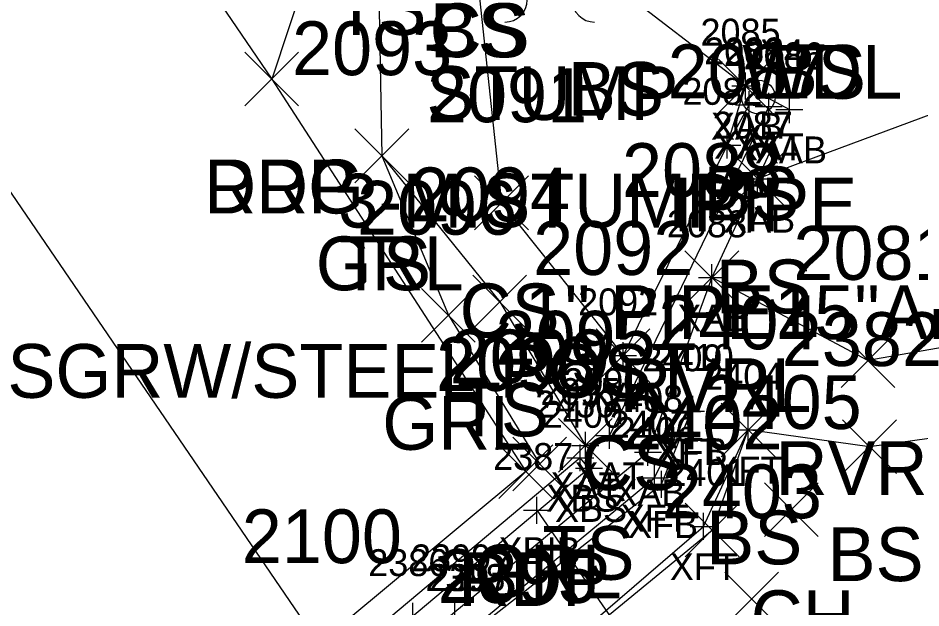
# Model space of a CAD drawing. Extents: x 1501299 to 1502485, y 381423 to 383765.
# Drawn here: x 1501597.62 to 1501631.17, y 383313.75 to 383335.68 of the extents above; entities that cross this region are included whole.
import ezdxf

# ---------------------------------------------------------------- set-up
doc = ezdxf.new("R2010")
doc.units = 0
for name, color, linetype in [('B_A', 7, 'Continuous'), ('B_I', 7, 'Continuous'), ('B_TIC', 7, 'Continuous'), ('BB', 7, 'Continuous'), ('BFT', 7, 'Continuous'), ('BSE', 7, 'Continuous'), ('BSUBM', 7, 'Continuous'), ('L_A', 7, 'Continuous'), ('L_C', 7, 'Continuous'), ('L_I', 7, 'Continuous'), ('L_TIC', 7, 'Continuous'), ('LAWE', 7, 'Continuous'), ('LELB', 7, 'Continuous'), ('LTS', 7, 'Continuous'), ('M_A', 7, 'Continuous'), ('M_C', 7, 'Continuous'), ('MPIP', 7, 'Continuous'), ('P_A', 7, 'Continuous'), ('P_I', 7, 'Continuous'), ('P_TIC', 7, 'Continuous'), ('PET', 7, 'Continuous'), ('PRC', 7, 'Continuous'), ('R_A', 7, 'Continuous'), ('R_C', 7, 'Continuous'), ('R_I', 7, 'Continuous'), ('R_TIC', 7, 'Continuous'), ('RDG', 7, 'Continuous'), ('RGR', 7, 'Continuous')]:
    doc.layers.add(name, color=color, linetype=linetype)

msp = doc.modelspace()

# ---------------------------------------------------------------- linework, layer by layer
at = {"layer": 'B_TIC'}
for p, q in [((1501624.647, 383333.16), (1501624.722, 383333.16)), ((1501624.781, 383332.46), (1501624.857, 383332.46)), ((1501625.516, 383332.398), (1501625.591, 383332.398)), ((1501626.279, 383332.279), (1501626.355, 383332.279)), ((1501623.974, 383330.957), (1501624.05, 383330.957)), ((1501623.974, 383330.957), (1501624.05, 383330.957)), ((1501623.974, 383330.957), (1501624.05, 383330.957)), ((1501625.099, 383329.703), (1501625.175, 383329.703)), ((1501623.399, 383326.029), (1501623.475, 383326.029)), ((1501620.1, 383323.129), (1501620.176, 383323.129)), ((1501622.491, 383321.046), (1501622.566, 383321.046)), ((1501622.626, 383321.06), (1501622.702, 383321.06)), ((1501624.75, 383320.366), (1501624.826, 383320.366)), ((1501619.591, 383320.161), (1501619.667, 383320.161)), ((1501618.699, 383319.793), (1501618.775, 383319.793)), ((1501618.511, 383319.328), (1501618.586, 383319.328)), ((1501621.024, 383319.534), (1501621.1, 383319.534)), ((1501621.024, 383319.534), (1501621.1, 383319.534)), ((1501618.832, 383318.945), (1501618.908, 383318.945)), ((1501621.272, 383318.583), (1501621.347, 383318.583)), ((1501621.523, 383318.346), (1501621.599, 383318.346)), ((1501616.903, 383317.377), (1501616.979, 383317.377)), ((1501623.094, 383316.78), (1501623.169, 383316.78))]:
    msp.add_line(p, q, dxfattribs=at)
for points in [[(1501624.643, 383332.66), (1501624.643, 383333.66)], [(1501624.143, 383333.16), (1501625.143, 383333.16)], [(1501624.778, 383331.96), (1501624.778, 383332.96)], [(1501625.512, 383331.898), (1501625.512, 383332.898)], [(1501626.276, 383331.779), (1501626.276, 383332.779)], [(1501624.278, 383332.46), (1501625.278, 383332.46)], [(1501625.012, 383332.398), (1501626.012, 383332.398)], [(1501625.776, 383332.279), (1501626.776, 383332.279)], [(1501623.971, 383330.457), (1501623.971, 383331.457)], [(1501623.971, 383330.457), (1501623.971, 383331.457)], [(1501623.971, 383330.457), (1501623.971, 383331.457)], [(1501623.471, 383330.957), (1501624.471, 383330.957)], [(1501623.471, 383330.957), (1501624.471, 383330.957)], [(1501623.471, 383330.957), (1501624.471, 383330.957)], [(1501625.096, 383329.203), (1501625.096, 383330.203)], [(1501624.596, 383329.703), (1501625.596, 383329.703)], [(1501623.396, 383325.529), (1501623.396, 383326.529)], [(1501622.896, 383326.029), (1501623.896, 383326.029)], [(1501620.097, 383322.629), (1501620.097, 383323.629)], [(1501619.597, 383323.129), (1501620.597, 383323.129)], [(1501622.487, 383320.546), (1501622.487, 383321.546)], [(1501622.623, 383320.56), (1501622.623, 383321.56)], [(1501621.987, 383321.046), (1501622.987, 383321.046)], [(1501622.123, 383321.06), (1501623.123, 383321.06)], [(1501619.588, 383319.661), (1501619.588, 383320.661)], [(1501624.747, 383319.866), (1501624.747, 383320.866)], [(1501624.247, 383320.366), (1501625.247, 383320.366)], [(1501618.696, 383319.293), (1501618.696, 383320.293)], [(1501619.088, 383320.161), (1501620.088, 383320.161)], [(1501621.021, 383319.034), (1501621.021, 383320.034)], [(1501621.021, 383319.034), (1501621.021, 383320.034)], [(1501618.196, 383319.793), (1501619.196, 383319.793)], [(1501618.507, 383318.828), (1501618.507, 383319.828)], [(1501618.007, 383319.328), (1501619.007, 383319.328)], [(1501618.829, 383318.445), (1501618.829, 383319.445)], [(1501620.521, 383319.534), (1501621.521, 383319.534)], [(1501620.521, 383319.534), (1501621.521, 383319.534)], [(1501621.268, 383318.083), (1501621.268, 383319.083)], [(1501618.329, 383318.945), (1501619.329, 383318.945)], [(1501621.52, 383317.846), (1501621.52, 383318.846)], [(1501620.768, 383318.583), (1501621.768, 383318.583)], [(1501621.02, 383318.346), (1501622.02, 383318.346)], [(1501616.9, 383316.877), (1501616.9, 383317.877)], [(1501616.4, 383317.377), (1501617.4, 383317.377)], [(1501623.09, 383316.28), (1501623.09, 383317.28)], [(1501622.59, 383316.78), (1501623.59, 383316.78)], [(1501612.287, 383312.93), (1501612.287, 383313.93)], [(1501613.853, 383313.107), (1501613.853, 383314.107)]]:
    msp.add_lwpolyline(points, dxfattribs=at)
at = {"layer": 'BB'}
msp.add_lwpolyline([(1501616.9, 383317.377), (1501632.264, 383295.097)], dxfattribs=at)
at = {"layer": 'BFT'}
for points in [[(1501591.846, 383302.634), (1501599.551, 383300.612), (1501608.842, 383308.268), (1501614.526, 383312.873), (1501621.52, 383318.346), (1501622.623, 383321.06)], [(1501591.893, 383302.71), (1501599.583, 383300.737), (1501608.715, 383308.273), (1501614.382, 383312.876), (1501621.268, 383318.583), (1501622.487, 383321.046)], [(1501590.258, 383300.858), (1501600.794, 383298.267), (1501604.985, 383301.7), (1501610.419, 383306.178), (1501616.429, 383311.032), (1501623.09, 383316.78), (1501624.747, 383320.366)]]:
    msp.add_lwpolyline(points, dxfattribs=at)
at = {"layer": 'BSE'}
msp.add_lwpolyline([(1501600.967, 383303.93), (1501618.829, 383318.945), (1501618.507, 383319.328), (1501600.646, 383304.313)], dxfattribs=at)
at = {"layer": 'BSUBM'}
for points in [[(1501623.971, 383330.957), (1501624.643, 383333.16), (1501626.276, 383332.279), (1501625.096, 383329.703), (1501623.396, 383326.029), (1501621.021, 383319.534)], [(1501623.971, 383330.957), (1501624.778, 383332.46), (1501625.512, 383332.398), (1501619.588, 383320.161), (1501618.696, 383319.793)], [(1501623.971, 383330.957), (1501620.097, 383323.129)], [(1501594.927, 383305.277), (1501590.251, 383306.118), (1501586.94, 383306.811), (1501586.804, 383304.65), (1501587.899, 383304.381), (1501591.885, 383303.599), (1501600.149, 383301.969), (1501608.182, 383308.826), (1501613.853, 383313.607), (1501621.021, 383319.534)]]:
    msp.add_lwpolyline(points, dxfattribs=at)
at = {"layer": 'L_TIC'}
for points in [[(1501623.643, 383332.16), (1501625.643, 383334.16)], [(1501625.643, 383332.16), (1501623.643, 383334.16)], [(1501610.136, 383329.56), (1501612.136, 383331.56)], [(1501612.136, 383329.56), (1501610.136, 383331.56)], [(1501624.096, 383328.703), (1501626.096, 383330.703)], [(1501626.096, 383328.703), (1501624.096, 383330.703)], [(1501614.583, 383327.811), (1501616.583, 383329.811)], [(1501616.583, 383327.811), (1501614.583, 383329.811)], [(1501622.396, 383325.029), (1501624.396, 383327.029)], [(1501624.396, 383325.029), (1501622.396, 383327.029)], [(1501614.516, 383324.125), (1501616.516, 383326.125)], [(1501616.516, 383324.125), (1501614.516, 383326.125)], [(1501619.097, 383322.129), (1501621.097, 383324.129)], [(1501621.097, 383322.129), (1501619.097, 383324.129)], [(1501628.198, 383321.948), (1501630.198, 383323.948)], [(1501630.198, 383321.948), (1501628.198, 383323.948)], [(1501623.747, 383319.366), (1501625.747, 383321.366)], [(1501625.747, 383319.366), (1501623.747, 383321.366)], [(1501623.747, 383319.366), (1501625.747, 383321.366)], [(1501625.747, 383319.366), (1501623.747, 383321.366)], [(1501617.696, 383318.793), (1501619.696, 383320.793)], [(1501619.696, 383318.793), (1501617.696, 383320.793)], [(1501628.255, 383318.743), (1501630.255, 383320.743)], [(1501630.255, 383318.743), (1501628.255, 383320.743)], [(1501625.351, 383316.401), (1501627.351, 383318.401)], [(1501627.351, 383316.401), (1501625.351, 383318.401)], [(1501622.409, 383315.642), (1501624.409, 383317.642)], [(1501624.409, 383315.642), (1501622.409, 383317.642)], [(1501623.877, 383313.082), (1501625.877, 383315.082)], [(1501625.877, 383313.082), (1501623.877, 383315.082)]]:
    msp.add_lwpolyline(points, dxfattribs=at)
at = {"layer": 'LAWE'}
msp.add_lwpolyline([(1501751.7, 383384.782), (1501736.295, 383377.69), (1501721.533, 383363.11), (1501708.276, 383357.65), (1501696.432, 383349.133), (1501679.062, 383342.719), (1501664.765, 383337.172), (1501649.638, 383330.877), (1501644.08, 383325.549), (1501629.198, 383322.948), (1501623.396, 383326.029)], dxfattribs=at)
at = {"layer": 'LELB'}
for points in [[(1501755, 383383.033), (1501740.914, 383377.326), (1501726.442, 383366.412), (1501710.788, 383355.524), (1501696.826, 383347.405), (1501681.956, 383338.634), (1501665.785, 383334.622), (1501652.745, 383328.441), (1501646.391, 383322.759), (1501637.585, 383320.905), (1501629.255, 383319.743), (1501624.747, 383320.366)], [(1501644.375, 383366.495), (1501627.025, 383352.911), (1501621.074, 383344.333), (1501614.47, 383339.228), (1501619.607, 383337.048), (1501624.643, 383333.16)], [(1501625.853, 383354.693), (1501616.397, 383345.622), (1501610.965, 383340.056), (1501611.136, 383330.56), (1501615.516, 383325.125), (1501618.696, 383319.793)], [(1501614.47, 383339.228), (1501615.583, 383328.811), (1501620.097, 383323.129)], [(1501637.668, 383334.383), (1501625.096, 383329.703)], [(1501498.194, 383229.3), (1501506.162, 383243.777), (1501514.118, 383255.518), (1501521.598, 383264.924), (1501530.006, 383266.909), (1501541.24, 383276.124), (1501565.518, 383288.263), (1501578.593, 383296.727), (1501585.352, 383299.258), (1501590.258, 383300.858), (1501600.796, 383297.995), (1501605.166, 383301.398), (1501610.699, 383306.054), (1501616.468, 383310.93), (1501623.409, 383316.642), (1501624.747, 383320.366)]]:
    msp.add_lwpolyline(points, dxfattribs=at)
at = {"layer": 'LTS'}
for centre, start, end in [((1501615.705, 383336.366), 270, 360), ((1501619.039, 383336.366), 180, 270)]:
    msp.add_arc(centre, 0.833, start, end, dxfattribs=at)
at = {"layer": 'MPIP'}
for radius in [0.625, 0.0833]:
    msp.add_circle((1501625.123, 383332.748), radius, dxfattribs=at)
at = {"layer": 'P_TIC'}
for points in [[(1501606.043, 383332.417), (1501608.043, 383334.417)], [(1501608.043, 383332.417), (1501606.043, 383334.417)], [(1501615.485, 383317.818), (1501617.485, 383319.818)], [(1501617.485, 383317.818), (1501615.485, 383319.818)]]:
    msp.add_lwpolyline(points, dxfattribs=at)
at = {"layer": 'PET'}
msp.add_lwpolyline([(1501352.609, 383730.103), (1501376.04, 383692.663), (1501392.886, 383664.453), (1501409.551, 383637.048), (1501431.218, 383601.012), (1501459.286, 383556.771), (1501480.727, 383522.39), (1501500.041, 383493.106), (1501518.668, 383465.088), (1501539.809, 383433.288), (1501559.66, 383403.845), (1501585.888, 383364.546), (1501607.043, 383333.417), (1501616.485, 383318.818), (1501608.79, 383312.411), (1501601.645, 383306.284)], dxfattribs=at)
at = {"layer": 'PRC'}
msp.add_lwpolyline([(1501342.033, 383724.182), (1501367.312, 383687.902), (1501383.586, 383659.523), (1501401.023, 383631.482), (1501422.762, 383595.527), (1501451.018, 383550.575), (1501471.941, 383517.221), (1501491.454, 383487.691), (1501510.587, 383459.001), (1501530.118, 383428.738), (1501550.992, 383398.393), (1501579.411, 383355.488), (1501608.79, 383312.411)], dxfattribs=at)
at = {"layer": 'R_TIC'}
for points in [[(1501606.043, 383332.417), (1501608.043, 383334.417)], [(1501608.043, 383332.417), (1501606.043, 383334.417)], [(1501610.136, 383329.56), (1501612.136, 383331.56)], [(1501612.136, 383329.56), (1501610.136, 383331.56)], [(1501612.607, 383323.628), (1501614.607, 383325.628)], [(1501614.607, 383323.628), (1501612.607, 383325.628)], [(1501616.002, 383318.098), (1501618.002, 383320.098)], [(1501618.002, 383318.098), (1501616.002, 383320.098)]]:
    msp.add_lwpolyline(points, dxfattribs=at)
at = {"layer": 'RDG'}
msp.add_lwpolyline([(1501733.479, 383413.356), (1501709.016, 383404.067), (1501690.807, 383395.363), (1501661.87, 383378.539), (1501644.375, 383366.495), (1501625.853, 383354.693), (1501614.404, 383347.477), (1501609.625, 383341.209), (1501607.043, 383333.417)], dxfattribs=at)
at = {"layer": 'RGR'}
msp.add_lwpolyline([(1501611.136, 383330.56), (1501613.607, 383324.628), (1501617.002, 383319.098)], dxfattribs=at)

# ---------------------------------------------------------------- texts
at = {"layer": 'B_A'}
for s, p in [('XAB', (1501623.364, 383331.16)), ('XAT', (1501623.483, 383330.46)), ('XAT', (1501624.217, 383330.398)), ('XAB', (1501624.996, 383330.279)), ('XAT', (1501622.675, 383328.957)), ('XAT', (1501622.675, 383328.957)), ('XAB', (1501622.691, 383328.957)), ('XAB', (1501623.816, 383327.703)), ('XAB', (1501622.116, 383324.029)), ('XAT', (1501618.801, 383321.129)), ('XFT', (1501621.231, 383319.046)), ('XFB', (1501621.383, 383319.06)), ('XFT', (1501623.491, 383318.366)), ('XAT', (1501618.293, 383318.161)), ('XAT', (1501617.4, 383317.793)), ('XBS', (1501617.247, 383317.328)), ('XAB', (1501619.741, 383317.534)), ('XAB', (1501619.741, 383317.534)), ('XBS', (1501617.569, 383316.945)), ('XFT', (1501620.012, 383316.583)), ('XFB', (1501620.28, 383316.346)), ('XBIB', (1501615.471, 383315.377)), ('XFT', (1501621.835, 383314.78))]:
    msp.add_text(s, height=1, dxfattribs=at).set_placement(p)
at = {"layer": 'B_I'}
for s, p in [('2085', (1501622.974, 383334.66)), ('2083', (1501623.109, 383333.96)), ('2084', (1501623.843, 383333.898)), ('2086', (1501624.579, 383333.779)), ('2082', (1501622.301, 383332.457)), ('2082', (1501622.301, 383332.457)), ('2082', (1501622.301, 383332.457)), ('2087', (1501623.427, 383331.203)), ('2088', (1501621.727, 383327.529)), ('2092', (1501618.427, 383324.629)), ('2409', (1501620.814, 383322.546)), ('2410', (1501621.233, 383322.56)), ('2090', (1501617.875, 383321.661)), ('2404', (1501623.077, 383321.866)), ('2095', (1501617.026, 383321.293)), ('2408', (1501619.352, 383321.034)), ('2408', (1501619.352, 383321.034)), ('2430', (1501616.834, 383320.828)), ('2400', (1501617.116, 383320.445)), ('2407', (1501619.599, 383320.083)), ('2406', (1501619.823, 383319.846)), ('2387', (1501615.27, 383318.877)), ('2401', (1501621.705, 383318.28)), ('2386', (1501610.63, 383314.93)), ('2399', (1501612.22, 383315.107)), ('2398', (1501612.752, 383314.376)), ('2397', (1501612.896, 383314.373))]:
    msp.add_text(s, height=1, dxfattribs=at).set_placement(p)
at = {"layer": 'L_A'}
for s, p in [('TS', (1501609.374, 383335.056)), ('CS', (1501612.911, 383334.228)), ('BS', (1501612.911, 383334.228)), ('WDL', (1501624.527, 383332.683)), ('BS', (1501625.551, 383332.683)), ('BS', (1501618.048, 383332.048)), ('STUMP', (1501612.793, 383331.893)), ('BS', (1501623.084, 383328.16)), ('TS', (1501609.546, 383325.56)), ('BS', (1501623.537, 383324.703)), ('CS', (1501614.024, 383323.811)), ('RVRL', (1501619.963, 383321.029)), ('TS', (1501613.925, 383320.125)), ('CS', (1501618.538, 383318.129)), ('RVRL', (1501625.765, 383317.948)), ('BS', (1501623.188, 383315.366)), ('BS', (1501623.188, 383315.366)), ('TS', (1501617.105, 383314.793)), ('BS', (1501627.696, 383314.743)), ('CH', (1501624.839, 383312.401))]:
    msp.add_text(s, height=2, dxfattribs=at).set_placement(p)
at = {"layer": 'L_C'}
msp.add_text('3-M.STUMP', height=2, dxfattribs=at).set_placement((1501609.517, 383327.893))
at = {"layer": 'L_I'}
for s, p in [('2093', (1501607.798, 383333.56)), ('2087', (1501621.757, 383332.703)), ('2091', (1501612.812, 383331.811)), ('2088', (1501620.057, 383329.029)), ('2094', (1501612.177, 383328.125)), ('2092', (1501616.758, 383326.129)), ('2081', (1501626.426, 383325.948)), ('2404', (1501621.408, 383323.366)), ('2404', (1501621.408, 383323.366)), ('2095', (1501615.357, 383322.793)), ('2382', (1501625.995, 383322.743)), ('2405', (1501623.013, 383320.401)), ('2402', (1501620.071, 383319.642)), ('2403', (1501621.538, 383317.082)), ('2395', (1501613.208, 383313.93))]:
    msp.add_text(s, height=2, dxfattribs=at).set_placement(p)
at = {"layer": 'M_A'}
msp.add_text('IPIPE', height=2, dxfattribs=at).set_placement((1501621.958, 383327.748))
at = {"layer": 'M_C'}
msp.add_text('1" PIPE15"ABG', height=2, dxfattribs=at).set_placement((1501616.439, 383323.748))
at = {"layer": 'P_A'}
for p in [(1501604.532, 383328.417), (1501613.973, 383313.818)]:
    msp.add_text('RDP', height=2, dxfattribs=at).set_placement(p)
at = {"layer": 'P_I'}
for s, p in [('2098', (1501613.147, 383321.818)), ('2100', (1501605.932, 383315.411)), ('2100', (1501605.932, 383315.411))]:
    msp.add_text(s, height=2, dxfattribs=at).set_placement(p)
at = {"layer": 'R_A'}
for s, p in [('DRG', (1501604.532, 383328.417)), ('GRL', (1501608.679, 383325.56)), ('GRL', (1501611.15, 383319.628)), ('GRL', (1501614.546, 383314.098))]:
    msp.add_text(s, height=2, dxfattribs=at).set_placement(p)
at = {"layer": 'R_C'}
msp.add_text('SGRW/STEEL POST', height=2, dxfattribs=at).set_placement((1501597.223, 383321.56))
at = {"layer": 'R_I'}
for s, p in [('2093', (1501607.798, 383333.56)), ('2096', (1501610.214, 383327.628)), ('2099', (1501613.656, 383322.098))]:
    msp.add_text(s, height=2, dxfattribs=at).set_placement(p)

doc.saveas('drawing.dxf')
